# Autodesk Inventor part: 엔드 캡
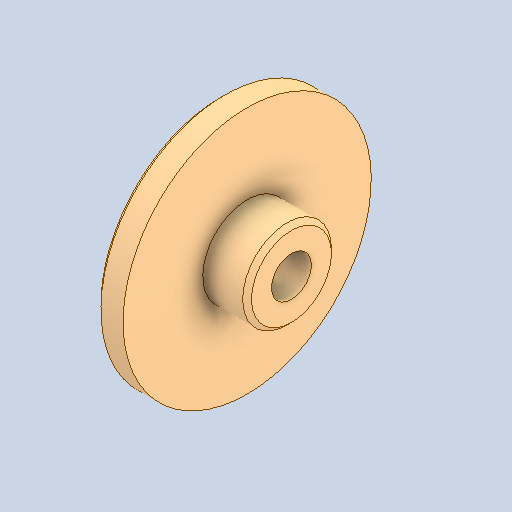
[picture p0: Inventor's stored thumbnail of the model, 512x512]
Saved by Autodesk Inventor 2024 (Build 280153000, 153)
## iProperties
Created: 2025-11
Part Number: 엔드 캡
Material: 강철, 연강
Document SubType Name: Modeling
Designer: Eud07
Density: 7.85 g/cm^3
Appearance: 기본값
Author: jhkim
Sending System: Autodesk Inventor 2026
Preprocessor: ST-DEVELOPER v20.1
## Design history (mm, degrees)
node "엔드 캡1"
node "솔리드2"
node "솔리드1"
